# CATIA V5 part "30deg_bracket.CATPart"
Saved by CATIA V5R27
Part number: 47065T32_T-Slotted Framing
Revision: ANY
Definition: UNKNOWN
Nomenclature: 47065T32_T-Slotted Framing
Source: Unknown
Bounding box of the stored display mesh (mm): x -38.1 to 38.1, y -44.45 to 44.45, z -3.175 to 3.175
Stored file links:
  \\triton.meca.polymtl.ca\usagers\zaoue\profiles\Desktop\varm_ass\structure prismatique\30deg_bracket.CATPart
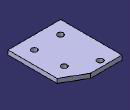
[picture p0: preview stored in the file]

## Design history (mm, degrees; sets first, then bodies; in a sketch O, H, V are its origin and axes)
Body1 "Imported1" (main body)
  Solid1: solid without history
